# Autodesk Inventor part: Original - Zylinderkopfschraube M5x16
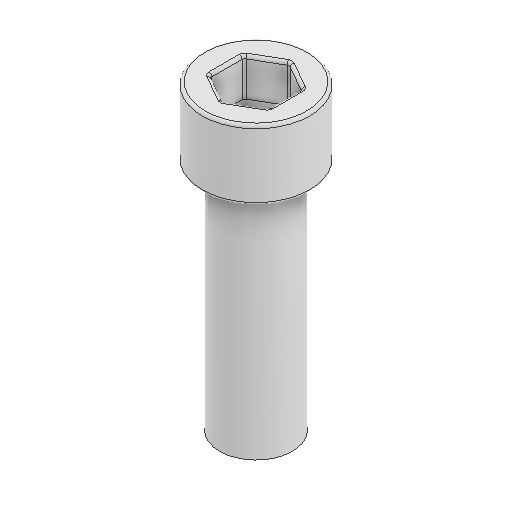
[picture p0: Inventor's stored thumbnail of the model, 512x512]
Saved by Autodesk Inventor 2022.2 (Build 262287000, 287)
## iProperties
Created: 2024-09
Part Number: Original - Zylinderkopfschraube M5x16
Material: Generico
Document SubType Name: Modeling
Designer: 18907419
Density: 1 g/cm^3
Appearance: Default
Author: 18907419
Revision Number: ANY
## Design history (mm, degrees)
feature "Verrundung3"
node "Solido1"
